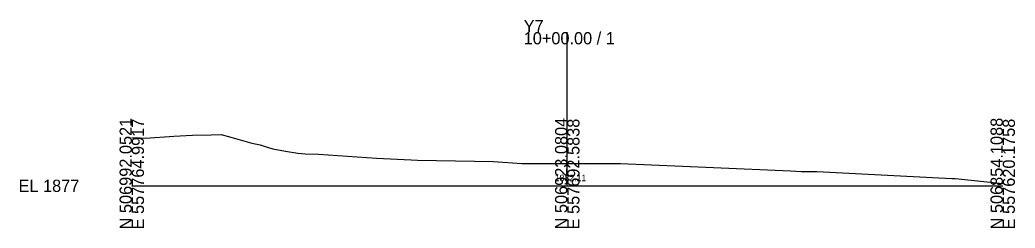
# Model space of a CAD drawing. Extents: x -26 to 557959, y -10 to 506992.
# Drawn here: x -25.7 to 202.8, y -9.7 to 38.1 of the extents above; entities that cross this region are included whole.
import ezdxf

# ---------------------------------------------------------------- set-up
doc = ezdxf.new("R2010")
doc.units = 0
for name, color, linetype in [('Default', 7, 'Continuous'), ('Exist Cross Section Cell', 7, 'Continuous'), ('Exist XS Center Line Elevation Label', 7, 'Continuous'), ('Exist XS Ground Line', 7, 'Continuous')]:
    doc.layers.add(name, color=color, linetype=linetype)

msp = doc.modelspace()

# ---------------------------------------------------------------- linework, layer by layer
at = {"layer": 'Exist Cross Section Cell'}
for p, q in [((100, 0), (100, 35.26)), ((0, 0), (100, 0)), ((100, 0), (200, 0))]:
    msp.add_line(p, q, dxfattribs=at)
at = {"layer": 'Exist XS Ground Line'}
for p, q in [((9.63, 11.4), (13.97, 11.61)), ((13.97, 11.61), (18.21, 11.71)), ((18.21, 11.71), (20.54, 11.75)), ((20.54, 11.75), (22.73, 11.17)), ((0, 11.08), (1.95, 11)), ((1.95, 11), (3.13, 10.97)), ((3.13, 10.97), (9.63, 11.4)), ((22.73, 11.17), (27.55, 9.78)), ((27.55, 9.78), (29.49, 9.37)), ((29.49, 9.37), (31.1, 8.85)), ((31.1, 8.85), (32.4, 8.48)), ((32.4, 8.48), (35.29, 7.99)), ((35.29, 7.99), (38.13, 7.52)), ((38.13, 7.52), (39.83, 7.36)), ((39.83, 7.36), (42.89, 7.25)), ((42.89, 7.25), (56.18, 6.35)), ((56.18, 6.35), (64.17, 5.93)), ((64.17, 5.93), (65.58, 5.87)), ((65.58, 5.87), (83.04, 5.55)), ((83.04, 5.55), (89.58, 5.14)), ((89.58, 5.14), (92.96, 5.1)), ((92.96, 5.1), (100, 5.11)), ((100, 5.11), (109.11, 5.11)), ((109.11, 5.11), (112.22, 5.09)), ((112.22, 5.09), (133.61, 4.18)), ((133.61, 4.18), (151.25, 3.41)), ((151.25, 3.41), (153.75, 3.31)), ((153.75, 3.31), (157.28, 3.32)), ((157.28, 3.32), (188.32, 1.69)), ((188.32, 1.69), (189.05, 1.66)), ((189.05, 1.66), (200, 0.5))]:
    msp.add_line(p, q, dxfattribs=at)

# ---------------------------------------------------------------- texts
at = {"layer": 'Default'}
msp.add_text('-', height=0.0001, dxfattribs=at).set_placement((0, 0))
at = {"layer": 'Exist Cross Section Cell'}
for s, p in [('Y7', (90, 35.26)), ('10+00.00 / 1', (90, 32.46)), ('EL 1877', (-26, -1.4))]:
    msp.add_text(s, height=2.8, dxfattribs=at).set_placement(p)
for s, p in [('N 506992.0521', (0, -10)), ('E 557764.9917', (2.8, -10)), ('N 506923.0804', (100, -10)), ('E 557692.5838', (102.8, -10)), ('N 506854.1088', (200, -10)), ('E 557620.1758', (202.8, -10))]:
    msp.add_text(s, height=2.8, rotation=90, dxfattribs=at).set_placement(p)
at = {"layer": 'Exist XS Center Line Elevation Label'}
msp.add_text('1882.11', height=1.5, dxfattribs=at).set_placement((97.11, 1.06))

doc.saveas('drawing.dxf')
